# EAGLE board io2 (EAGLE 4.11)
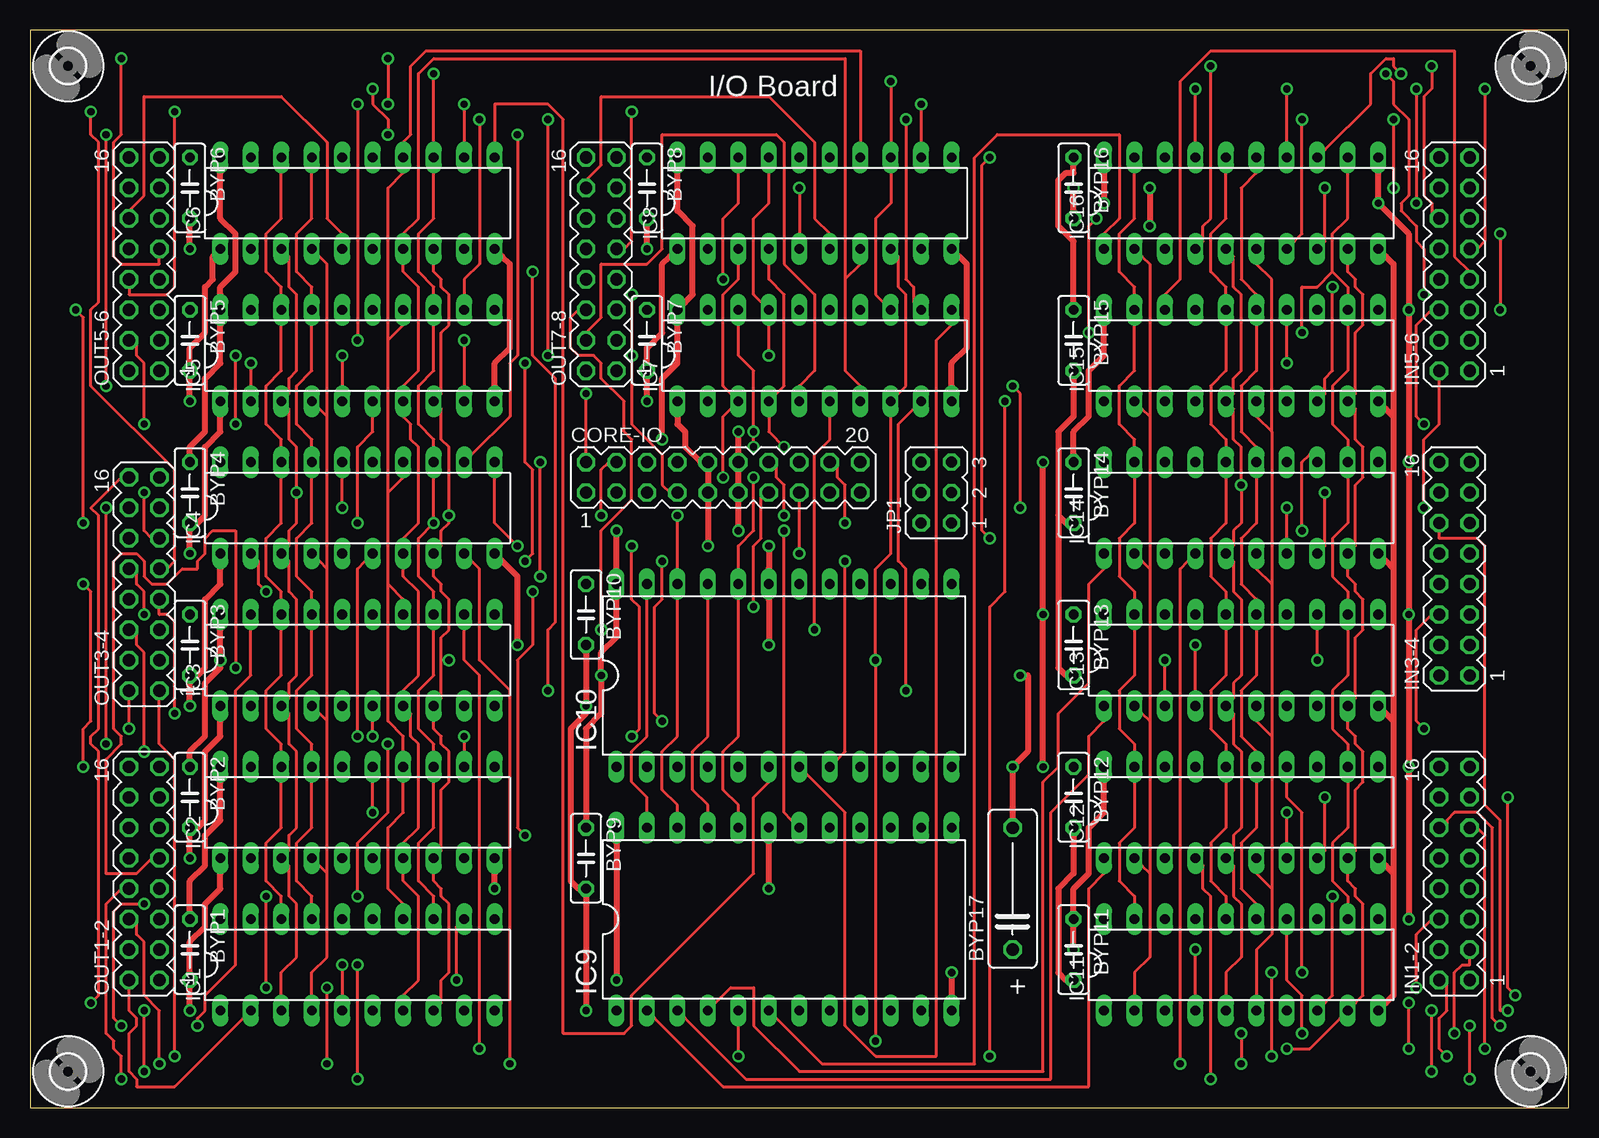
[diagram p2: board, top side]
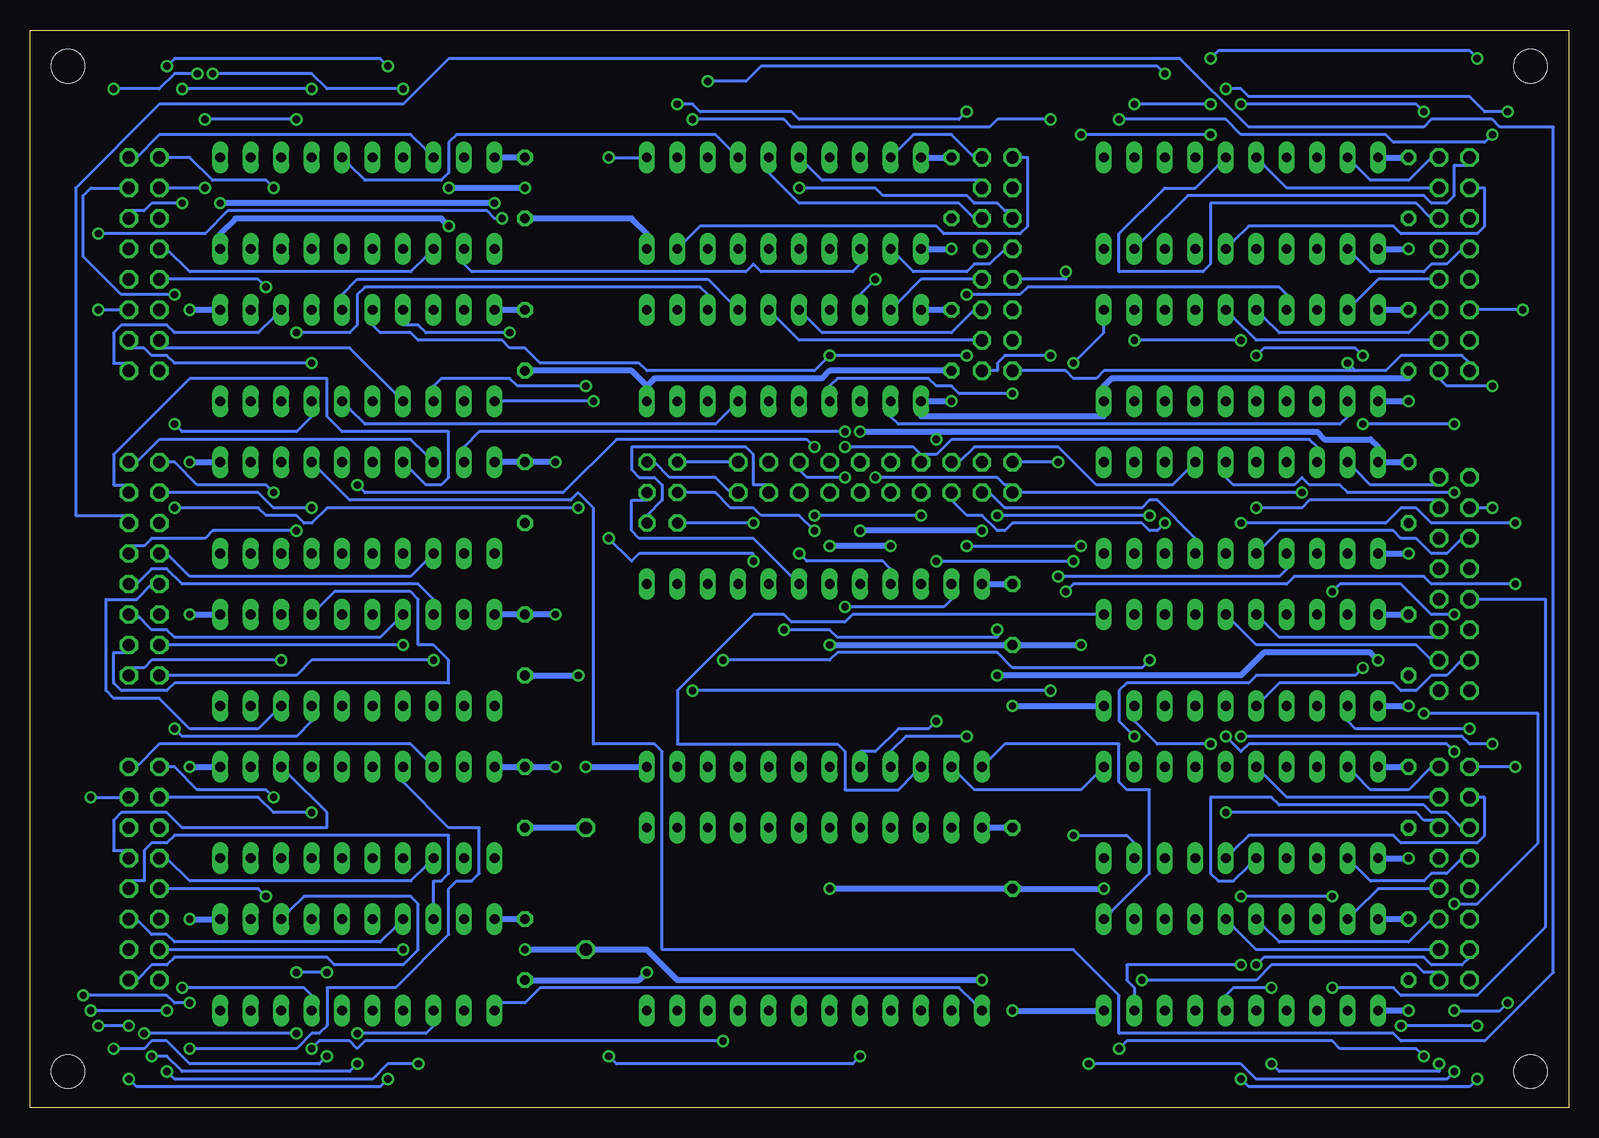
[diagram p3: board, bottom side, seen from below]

Size 128.25 x 89.84 mm. Coordinates in mm from the lower left corner, seen from the top.
Outline: 0,0 128.25,0 128.25,89.84 0,89.84 0,0
Copper layers (1*16): Top 0.035mm / dielectric 1.5mm / Bottom 0.035mm
Design rules "default": minimum track width 10mil, minimum drill 24mil, track to track 8mil, track to pad 8mil, pad to pad 8mil, via to via 8mil, smd to smd 8mil, copper to edge 40mil, drill to drill 8mil, minimum pad ring 10mil, minimum via ring 8mil, stop-mask expansion 4mil, vias tented up to drill 0mil, thermal gap 10mil
Net classes: 1 Power: width 0.508 mm, drill 0.254 mm, clearance 0.254 mm

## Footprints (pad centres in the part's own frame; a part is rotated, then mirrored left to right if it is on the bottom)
C050-025X075 = drill 0.813 octagon: 1 -2.54,0; 2 2.54,0
C102-043X133 = drill 1.016 octagon: 1 -5.08,0; 2 5.08,0
MA10-2 = drill 1.016 octagon: 1 -11.43,-1.27; 2 -11.43,1.27; 3 -8.89,-1.27; 4 -8.89,1.27; 5 -6.35,-1.27; 6 -6.35,1.27; 7 -3.81,-1.27; 8 -3.81,1.27; 9 -1.27,-1.27; 10 -1.27,1.27; 11 1.27,-1.27; 12 1.27,1.27; 13 3.81,-1.27; 14 3.81,1.27; 15 6.35,-1.27; 16 6.35,1.27; 17 8.89,-1.27; 18 8.89,1.27; 19 11.43,-1.27; 20 11.43,1.27
DIL20 = drill 0.813 long: 1 -11.43,-3.81; 2 -8.89,-3.81; 3 -6.35,-3.81; 4 -3.81,-3.81; 5 -1.27,-3.81; 6 1.27,-3.81; 7 3.81,-3.81; 8 6.35,-3.81; 9 8.89,-3.81; 10 11.43,-3.81; 11 11.43,3.81; 12 8.89,3.81; 13 6.35,3.81; 14 3.81,3.81; 15 1.27,3.81; 16 -1.27,3.81; 17 -3.81,3.81; 18 -6.35,3.81; 19 -8.89,3.81; 20 -11.43,3.81
DIL24-6 = drill 0.813 long: 1 -13.97,-7.62; 2 -11.43,-7.62; 3 -8.89,-7.62; 4 -6.35,-7.62; 5 -3.81,-7.62; 6 -1.27,-7.62; 7 1.27,-7.62; 8 3.81,-7.62; 9 6.35,-7.62; 10 8.89,-7.62; 11 11.43,-7.62; 12 13.97,-7.62; 13 13.97,7.62; 14 11.43,7.62; 15 8.89,7.62; 16 6.35,7.62; 17 3.81,7.62; 18 1.27,7.62; 19 -1.27,7.62; 20 -3.81,7.62; 21 -6.35,7.62; 22 -8.89,7.62; 23 -11.43,7.62; 24 -13.97,7.62
MA08-2 = drill 1.016 octagon: 1 -8.89,-1.27; 2 -8.89,1.27; 3 -6.35,-1.27; 4 -6.35,1.27; 5 -3.81,-1.27; 6 -3.81,1.27; 7 -1.27,-1.27; 8 -1.27,1.27; 9 1.27,-1.27; 10 1.27,1.27; 11 3.81,-1.27; 12 3.81,1.27; 13 6.35,-1.27; 14 6.35,1.27; 15 8.89,-1.27; 16 8.89,1.27
JP3Q = drill 0.914 octagon: 1 -2.54,-1.27; 2 -2.54,1.27; 3 0,-1.27; 4 0,1.27; 5 2.54,-1.27; 6 2.54,1.27
2,8 = hole 2.8: 0,0

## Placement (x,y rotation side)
BYP1  .01uf  [C050-025X075]  13.33,13.17 270 top
BYP2  .01uf  [C050-025X075]  13.33,25.87 270 top
BYP3  .01uf  [C050-025X075]  13.33,38.57 270 top
BYP4  .01uf  [C050-025X075]  13.33,51.27 270 top
BYP5  .01uf  [C050-025X075]  13.33,63.97 270 top
BYP6  .01uf  [C050-025X075]  13.33,76.67 270 top
BYP7  .01uf  [C050-025X075]  51.43,63.97 270 top
BYP8  .01uf  [C050-025X075]  51.43,76.67 270 top
BYP9  .01uf  [C050-025X075]  46.35,20.79 270 top
BYP10  .01uf  [C050-025X075]  46.35,41.11 270 top
BYP11  .01uf  [C050-025X075]  86.99,13.17 270 top
BYP12  .01uf  [C050-025X075]  86.99,25.87 270 top
BYP13  .01uf  [C050-025X075]  86.99,38.57 270 top
BYP14  .01uf  [C050-025X075]  86.99,51.27 270 top
BYP15  .01uf  [C050-025X075]  86.99,63.97 270 top
BYP16  .01uf  [C050-025X075]  86.99,76.67 270 top
BYP17  100uf 25V  [C102-043X133]  81.91,18.25 90 top
CORE-IO  [MA10-2]  57.78,52.54 0 top
IC1  74LS374N  [DIL20]  27.3,11.9 0 top
IC2  74LS374N  [DIL20]  27.3,24.6 0 top
IC3  74LS374N  [DIL20]  27.3,37.3 0 top
IC4  74LS374N  [DIL20]  27.3,50 0 top
IC5  74LS374N  [DIL20]  27.3,62.7 0 top
IC6  74LS374N  [DIL20]  27.3,75.4 0 top
IC7  74LS374N  [DIL20]  65.4,62.7 0 top
IC8  74LS374N  [DIL20]  65.4,75.4 0 top
IC9  74154N  [DIL24-6]  62.86,15.71 0 top
IC10  74154N  [DIL24-6]  62.86,36.03 0 top
IC11  74LS373N  [DIL20]  100.96,11.9 0 top
IC12  74LS373N  [DIL20]  100.96,24.6 0 top
IC13  74LS373N  [DIL20]  100.96,37.3 0 top
IC14  74LS373N  [DIL20]  100.96,50 0 top
IC15  74LS373N  [DIL20]  100.96,62.7 0 top
IC16  74LS373N  [DIL20]  100.96,75.4 0 top
IN1-2  [MA08-2]  118.74,19.52 90 top
IN3-4  [MA08-2]  118.74,44.92 90 top
IN5-6  [MA08-2]  118.74,70.32 90 top
JP1  [JP3Q]  75.56,51.27 90 top
OUT1-2  [MA08-2]  9.52,19.52 90 top
OUT3-4  [MA08-2]  9.52,43.65 90 top
OUT5-6  [MA08-2]  9.52,70.32 90 top
OUT7-8  [MA08-2]  47.62,70.32 90 top
U$1  [2,8]  125.09,3.01 0 top
U$2  [2,8]  125.09,86.83 0 top
U$3  [2,8]  3.17,86.83 0 top
U$4  [2,8]  3.17,3.01 0 top

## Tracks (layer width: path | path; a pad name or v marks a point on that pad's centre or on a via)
GND  (via drill 0.61)
  Top 0.508: 113.66,19.52 113.66,9.36 113.02,8.73 IC11.10 | 113.66,19.52 113.02,20.15 IC12.10 | 113.66,32.22 113.02,32.85 IC13.10 | 113.66,32.22 113.66,19.52 | 113.66,44.92 113.02,45.55 IC14.10 | 113.66,44.92 113.66,32.22 | 113.66,57.62 113.02,58.25 IC15.10 | 113.66,57.62 113.66,44.92 | 113.66,57.62 113.66,70.32 113.02,70.95 IC16.10 | 85.72,49.37 86.35,48.73 BYP14.2 | 85.72,49.37 85.72,56.35 86.99,57.62 86.99,60.8 BYP15.2 | IC8.10 77.46,70.95 78.1,70.32 78.1,63.34 76.83,62.06 76.83,60.16 IC7.10 | v76.83,11.27 76.83,9.36 IC9.12 | BYP17.2 81.91,23.96 v81.91,28.41 83.18,29.68 83.18,36.03 v82.55,36.03 | BYP11.2 86.35,10.63 85.72,11.27 85.72,18.25 86.99,19.52 86.99,22.7 BYP12.2 | 85.72,49.37 85.72,36.66 86.35,36.03 BYP13.2 | v93.34,76.67 v93.34,73.5 | v86.99,76.67 86.99,74.77 BYP16.2 | v13.33,8.09 13.33,10 BYP1.2 13.33,11.27 13.33,13.81 14.6,15.08 14.6,16.98 15.87,18.25 15.87,19.52 IC2.1 | v13.33,20.79 13.33,22.7 BYP2.2 13.97,23.33 14.6,23.96 14.6,29.68 15.87,30.95 15.87,32.22 IC3.1 | v13.33,71.59 13.33,73.5 BYP6.2 | v13.33,58.89 13.33,60.8 BYP5.2 13.33,62.06 13.33,63.34 14.6,64.61 14.6,68.41 15.24,69.05 15.24,70.95 IC6.1 | v13.33,33.49 13.33,35.39 BYP3.2 13.97,36.03 14.6,36.66 14.6,42.38 15.87,43.65 15.87,44.92 IC4.1 | v13.33,46.19 13.33,48.09 BYP4.2 13.97,48.73 14.6,49.37 14.6,55.08 15.87,56.35 15.87,57.62 IC5.1 | v46.35,8.09 46.35,17.61 BYP9.2 45.72,18.25 45.08,18.88 45.08,31.58 46.35,32.85 v46.35,33.49 46.35,37.94 BYP10.2 | v38.73,18.25 38.73,19.52 IC2.10 | v61.59,18.25 61.59,22.06 IC9.19 | v40.64,38.57 40.64,44.28 39.37,45.55 IC4.10 | v61.59,38.57 61.59,42.38 IC10.19 61.59,44.92 v61.59,46.82
  Top 0.508: v51.43,71.59 51.43,73.5 BYP8.2 | IC6.10 39.37,70.95 40,70.32 40,63.34 38.73,62.06 38.73,60.16 IC5.10 | v51.43,58.89 51.43,60.8 BYP7.2 51.43,62.06 51.43,63.34 52.7,64.61 52.7,70.32 53.34,70.95 IC8.1 | IC7.1 53.97,57.62 53.97,56.98 54.61,56.35 54.61,55.08 55.88,53.81 CORE-IO.10 56.51,53.17 56.51,51.91 CORE-IO.9 56.51,50.63 v56.51,46.82
  Bottom 0.508: IC8.10 76.83,72.86 78.1,74.13 86.35,74.13 BYP16.2 | 76.83,60.16 78.1,61.43 86.35,61.43 BYP15.2 | 76.83,60.16 IC7.10 76.83,60.16 | v76.83,11.27 77.46,10.63 86.35,10.63 BYP11.2 | v81.91,28.41 77.46,28.41 IC10.12 | BYP12.2 86.35,23.33 82.55,23.33 BYP17.2 | v82.55,36.03 86.35,36.03 BYP13.2 | v93.34,73.5 93.97,74.13 111.12,74.13 112.39,72.86 IC16.10 | v86.99,76.67 v93.34,76.67 | v13.33,8.09 15.24,8.09 IC1.1 | v13.33,20.79 15.24,20.79 IC2.1 | v13.33,71.59 15.24,71.59 IC6.1 | v13.33,58.89 15.24,58.89 IC5.1 | v13.33,33.49 15.24,33.49 IC3.1 | v13.33,46.19 15.24,46.19 IC4.1 | v46.35,8.09 39.37,8.09 IC1.10 | v38.73,18.25 45.72,18.25 BYP9.2 46.98,18.25 v61.59,18.25 | v46.35,33.49 39.37,33.49 IC3.10 | v40.64,38.57 45.72,38.57 BYP10.2 46.98,38.57 v61.59,38.57 | v51.43,71.59 53.34,71.59 IC8.1 | v51.43,58.89 53.34,58.89 IC7.1 53.97,57.62 38.73,57.62 IC5.10 38.73,60.16 38.1,60.8 13.33,60.8 BYP5.2 | v56.51,46.82 v61.59,46.82 | 76.83,60.16 76.19,60.8 62.23,60.8 61.59,61.43 52.07,61.43 BYP7.2
IN00
  Bottom 0.254: IC9.1 49.53,8.73 50.8,10 85.72,10 86.99,8.73 88.89,8.73 IC11.1
IN01
  Top 0.254: IC9.2 52.07,7.46 57.78,1.74 88.26,1.74 88.26,18.25 89.53,19.52 IC12.1
IN02
  Top 0.254: IC9.3 54.61,7.46 59.69,2.38 85.08,2.38 85.08,24.6 88.26,27.77 88.26,30.95 89.53,32.22 IC13.1
IN03
  Top 0.254: IC9.4 57.15,8.73 58.41,10 60.32,10 60.32,6.82 64.13,3.01 84.45,3.01 84.45,27.14 85.72,28.41 85.72,32.85 88.26,35.39 88.26,43.65 89.53,44.92 IC14.1
IN04  (via drill 0.61)
  Top 0.254: v59.05,4.28 59.05,6.82 IC9.5 | v80,4.28 80,41.74 81.27,43.02 v81.27,58.89
  Bottom 0.254: v59.05,4.28 59.69,3.64 79.37,3.64 v80,4.28 | v81.27,58.89 88.89,58.89 IC15.1
IN05
  Top 0.254: IC9.6 62.23,7.46 66.03,3.64 78.73,3.64 78.73,79.21 80.64,81.11 90.8,81.11 90.8,74.13 89.53,72.86 IC16.1
ISEL  (via drill 0.61)
  Top 0.254: v62.86,48.09 62.86,24.6 63.5,23.96 IC9.18
  Bottom 0.254: v62.86,48.09 64.13,49.37 67.3,49.37 67.94,50 69.84,50 71.11,51.27 73.66,51.27 JP1.4
N$1
  Bottom 0.254: IC12.3 95.24,20.15 96.52,18.88 114.93,18.88 116.83,20.79 IN1-2.10
N$2  (via drill 0.61)
  Top 0.254: v98.42,2.38 98.42,17.61 97.78,18.25 97.78,20.15 IC12.4 | v120.01,2.38 v120.01,6.82 | v122.55,6.82 121.91,7.46 121.91,23.33 120.64,24.6 118.74,24.6 118.1,23.96 118.1,23.33 IN1-2.12
  Bottom 0.254: v98.42,2.38 99.05,1.74 119.38,1.74 v120.01,2.38 | v120.01,6.82 v122.55,6.82
N$7  (via drill 0.61)
  Top 0.254: v104.77,24.6 104.77,22.06 IC12.7
  Bottom 0.254: v104.77,24.6 107.94,24.6 109.21,25.87 116.83,25.87 IN1-2.14
N$8  (via drill 0.61)
  Top 0.254: v107.94,25.87 107.94,21.42 IC12.8
  Bottom 0.254: v107.94,25.87 108.58,26.5 114.3,26.5 116.2,28.41 116.83,28.41 IN1-2.16
N$9  (via drill 0.61)
  Top 0.254: v108.58,17.61 108.58,9.36 107.94,8.73 IC11.8
  Bottom 0.254: v108.58,17.61 109.21,18.25 116.83,18.25 IN1-2.8
N$10  (via drill 0.61)
  Top 0.254: v115.56,10 115.56,14.44 116.83,15.71 IN1-2.6
  Bottom 0.254: v115.56,10 105.41,10 104.77,9.36 IC11.7
N$11  (via drill 0.61)
  Top 0.254: v97.15,13.17 97.15,9.36 IC11.4
  Bottom 0.254: v97.15,13.17 116.83,13.17 IN1-2.4
N$12  (via drill 0.61)
  Top 0.254: v100.96,6.18 v100.96,3.64 | v118.1,4.28 117.47,4.92 117.47,7.46 118.1,8.09 118.1,10.63 IN1-2.2
  Bottom 0.254: v100.96,6.18 95.24,6.18 94.61,6.82 IC11.3 | v100.96,3.64 101.59,3.01 115.56,3.01 116.83,4.28 v118.1,4.28
N$13
  Bottom 0.254: IC11.13 106.67,16.34 105.41,17.61 96.52,17.61 95.88,16.98 95.88,13.17 97.15,11.9 102.86,11.9 103.5,12.54 116.2,12.54 116.83,11.9 118.1,11.9 119.38,10.63 IN1-2.1
N$14  (via drill 0.61)
  Top 0.254: v106.04,6.18 106.04,9.36 104.77,10.63 104.77,14.44 IC11.14 | v118.74,6.18 118.74,11.27 119.38,11.9 120.01,11.9 120.01,12.54 IN1-2.3
  Bottom 0.254: v106.04,6.18 v118.74,6.18
N$15
  Bottom 0.254: IC11.17 97.78,15.08 99.05,13.81 116.2,13.81 116.83,14.44 118.1,14.44 119.38,15.71 IN1-2.5
N$16
  Bottom 0.254: IC11.18 94.61,16.98 94.61,18.88 93.97,18.88 93.34,19.52 93.34,22.7 116.2,22.7 116.83,22.06 118.1,22.06 118.74,21.42 118.74,18.88 120.01,18.88 IN1-2.7
N$17
  Bottom 0.254: IC12.13 106.67,27.77 103.5,24.6 103.5,23.33 115.56,23.33 116.83,24.6 120.64,24.6 121.28,23.96 121.28,21.42 120.01,21.42 IN1-2.9
N$18  (via drill 0.61)
  Top 0.254: v121.28,4.92 121.28,22.7 120.64,23.33 IN1-2.11 | v103.5,4.28 v103.5,11.27 | v106.04,11.27 106.04,24.6 104.77,25.87 104.77,27.14 IC12.14
  Bottom 0.254: v121.28,4.92 118.74,4.92 118.1,5.55 116.83,5.55 114.93,3.64 104.13,3.64 v103.5,4.28 | v103.5,11.27 v106.04,11.27
N$19  (via drill 0.61)
  Top 0.254: v123.19,25.87 123.19,10 v123.82,9.36 | v114.93,4.92 v114.93,8.73
  Bottom 0.254: v123.19,25.87 120.64,25.87 IN1-2.13 | v123.82,9.36 116.83,9.36 116.2,8.73 v114.93,8.73 | v114.93,4.92 106.04,4.92 104.77,6.18 104.13,6.18 103.5,6.82 103.5,10 97.78,10 93.34,14.44 93.34,18.25 92.7,18.88 91.44,18.88 90.8,19.52 90.8,23.33 93.34,23.33 97.15,27.14 IC12.17
N$20
  Bottom 0.254: IC12.18 95.24,29.04 96.52,30.31 117.47,30.31 119.38,28.41 IN1-2.15
N$26  (via drill 0.61)
  Top 0.254: v18.41,62.06 18.41,60.16 IC5.2
  Bottom 0.254: 17.77,61.43 15.24,61.43 13.97,62.7 8.89,62.7 8.25,62.06 OUT5-6.2 | 17.77,61.43 v18.41,62.06 | IC7.2 56.51,57.62 55.88,56.98 19.04,56.98 18.41,57.62 IC5.2 | 17.77,61.43 38.73,61.43 39.37,60.8 41.27,60.8 41.91,61.43 45.72,61.43 OUT7-8.2
N$29
  Bottom 0.254: IC14.3 95.24,45.55 96.52,44.28 114.93,44.28 116.83,46.19 IN3-4.10
N$30  (via drill 0.61)
  Top 0.254: v95.88,3.64 95.88,44.92 96.52,45.55 IC14.4 | v116.83,3.01 v116.83,8.09 | v123.19,8.09 122.55,8.09 122.55,23.96 121.28,25.23 121.28,46.82 120.64,47.46 117.47,47.46 117.47,48.09 IN3-4.12
  Bottom 0.254: v95.88,3.64 98.42,3.64 99.69,2.38 116.2,2.38 v116.83,3.01 | v116.83,8.09 v123.19,8.09
N$31  (via drill 0.61)
  Top 0.254: v104.77,50 104.77,47.46 IC14.7
  Bottom 0.254: v104.77,50 107.94,50 109.21,51.27 116.83,51.27 IN3-4.14
N$32  (via drill 0.61)
  Top 0.254: v107.94,51.27 107.94,46.82 IC14.8
  Bottom 0.254: v107.94,51.27 108.58,51.91 114.3,51.91 116.2,53.81 116.83,53.81 IN3-4.16
N$33  (via drill 0.61)
  Top 0.254: v37.46,4.92 37.46,36.03 36.19,37.3 36.19,39.84 IC3.12 | v12.06,4.28 12.06,29.04 10.79,30.31 10.79,34.12 OUT3-4.1
  Bottom 0.254: v37.46,4.92 36.83,5.55 19.68,5.55 19.04,4.92 12.7,4.92 v12.06,4.28
N$34
  Bottom 0.254: IC3.15 27.93,40.48 26.03,38.57 12.7,38.57 11.43,37.3 OUT3-4.3
N$35
  Bottom 0.254: IC3.16 25.39,40.48 24.12,39.2 10.79,39.2 OUT3-4.5
N$36  (via drill 0.61)
  Top 0.254: v13.97,6.82 13.97,7.46 14.6,8.09 14.6,9.36 17.14,11.9 17.14,34.76 18.41,36.03 18.41,39.84 IC3.19 | v7.62,6.82 6.98,7.46 6.98,16.34 7.62,16.98 v9.52,16.98 | v12.06,32.85 12.06,40.48 11.43,41.11 10.79,41.11 10.79,41.74 OUT3-4.7
  Bottom 0.254: v7.62,6.82 v13.97,6.82 | v9.52,16.98 7.62,16.98 2.54,22.06 2.54,32.85 v12.06,32.85
N$37  (via drill 0.61)
  Top 0.254: v94.61,37.3 94.61,34.76 IC13.3
  Bottom 0.254: v94.61,37.3 104.77,37.3 106.04,36.03 116.83,36.03 IN3-4.2
N$38  (via drill 0.61)
  Top 0.254: v97.15,38.57 97.15,34.76 IC13.4
  Bottom 0.254: v97.15,38.57 116.83,38.57 IN3-4.4
N$39  (via drill 0.61)
  Top 0.254: v116.2,31.58 115.56,32.22 115.56,39.84 116.83,41.11 IN3-4.6
  Bottom 0.254: v116.2,31.58 115.56,30.95 106.04,30.95 104.77,32.22 IC13.7
N$40
  Bottom 0.254: IC13.8 107.94,32.85 109.21,31.58 114.93,31.58 117.47,34.12 121.28,34.12 121.91,34.76 121.91,42.38 119.38,42.38 118.1,43.65 IN3-4.8
N$41  (via drill 0.61)
  Top 0.254: v106.04,48.09 106.04,53.81 106.67,54.45 IC14.13
  Bottom 0.254: v106.04,48.09 113.02,48.09 113.66,47.46 118.1,47.46 118.74,46.82 120.01,46.82 IN3-4.9
N$42
  Bottom 0.254: IC14.14 104.13,53.17 101.59,50.63 83.18,50.63 82.55,51.27 81.27,50 81.27,30.31 76.19,30.31 75.56,29.68 75.56,13.17 41.27,13.17 37.46,9.36 37.46,6.18 14.6,6.18 13.97,5.55 6.98,5.55 1.27,11.27 1.27,81.75 5.71,81.75 6.34,82.39 11.43,82.39 12.06,81.75 26.66,81.75 32.38,87.47 93.34,87.47 97.15,83.66 117.47,83.66 124.45,76.67 124.45,49.37 120.01,49.37 IN3-4.11
N$43
  Bottom 0.254: IC14.17 96.52,53.17 95.24,51.91 93.97,51.91 93.34,52.54 93.34,56.35 102.23,56.35 103.5,57.62 103.5,60.8 114.93,60.8 121.28,54.45 121.28,51.91 120.01,51.91 IN3-4.13
N$44
  Bottom 0.254: IC14.18 95.24,54.45 96.52,55.71 117.47,55.71 119.38,53.81 IN3-4.15
N$45  (via drill 0.61)
  Top 0.254: v107.31,37.3 107.31,39.84 IC13.13
  Bottom 0.254: v107.31,37.3 118.1,37.3 118.74,36.66 120.01,36.66 IN3-4.1
N$46
  Bottom 0.254: IC13.14 104.13,41.74 102.86,43.02 96.52,43.02 95.88,42.38 95.88,38.57 94.61,38.57 93.34,37.3 93.34,35.39 116.2,35.39 116.83,34.76 120.64,34.76 121.28,35.39 121.28,37.94 120.01,37.94 IN3-4.3
N$47
  Bottom 0.254: IC13.17 97.78,40.48 99.05,39.2 116.2,39.2 116.83,39.84 118.1,39.84 119.38,41.11 IN3-4.5
N$48
  Bottom 0.254: IC13.18 94.61,42.38 95.88,43.65 115.56,43.65 116.83,44.92 118.1,44.92 119.38,43.65 IN3-4.7
N$49
  Bottom 0.254: IC3.5 25.39,34.12 24.12,35.39 14.6,35.39 13.97,34.76 12.7,34.76 11.43,36.03 10.16,36.03 8.89,37.3 OUT3-4.4
N$50  (via drill 0.61)
  Top 0.254: v28.57,30.95 28.57,32.22 IC3.6 | v9.52,29.68 9.52,37.94 8.89,38.57 8.89,39.84 OUT3-4.6
  Bottom 0.254: v28.57,30.95 27.3,29.68 26.66,30.31 10.16,30.31 v9.52,29.68
N$51  (via drill 0.61)
  Top 0.254: v8.25,31.58 8.25,34.12 OUT3-4.2
  Bottom 0.254: v8.25,31.58 17.77,31.58 18.41,32.22 IC3.2
N$52  (via drill 0.61)
  Top 0.254: v29.84,30.31 29.84,24.6 27.3,22.06 v27.3,17.61 | v19.68,10 v19.68,17.61
  Bottom 0.254: v29.84,30.31 34.29,30.31 36.19,32.22 IC3.9 | v19.68,17.61 v27.3,17.61 | v19.68,10 14.6,10 13.97,9.36 7.62,9.36 1.9,15.08 1.9,42.38 7.62,42.38 OUT3-4.8
N$53  (via drill 0.61)
  Top 0.254: v35.55,10.63 35.55,15.08 IC1.12
  Bottom 0.254: v35.55,10.63 26.03,10.63 24.76,11.9 12.7,11.9 12.06,11.27 10.79,11.27 OUT1-2.1
N$54
  Bottom 0.254: IC1.15 27.93,15.08 26.03,13.17 11.43,13.17 OUT1-2.3
N$55
  Bottom 0.254: IC1.16 25.39,15.08 24.12,13.81 13.33,13.81 11.43,15.71 OUT1-2.5
N$56
  Bottom 0.254: IC1.19 17.77,16.34 15.87,18.25 11.43,18.25 OUT1-2.7
N$57
  Top 0.254: IC1.2 17.77,7.46 12.06,1.74 8.89,1.74 8.89,2.38 8.25,3.01 8.25,6.18 8.89,6.82 8.89,7.46 8.25,8.09 8.25,10 OUT1-2.2
N$58  (via drill 0.61)
  Top 0.254: v26.03,11.9 26.03,9.36 IC1.5
  Bottom 0.254: v26.03,11.9 25.39,12.54 12.06,12.54 11.43,11.9 8.89,11.9 8.25,12.54 OUT1-2.4
N$59  (via drill 0.61)
  Top 0.254: v10.79,3.64 10.79,8.09 9.52,9.36 9.52,13.81 8.89,14.44 8.89,15.71 OUT1-2.6 | v24.76,3.64 v24.76,10
  Bottom 0.254: v10.79,3.64 10.79,3.01 24.12,3.01 v24.76,3.64 | v24.76,10 27.93,10 28.57,9.36 IC1.6
N$60  (via drill 0.61)
  Top 0.254: v27.3,2.38 v27.3,11.9 | v7.62,2.38 7.62,4.28 6.98,4.92 6.98,5.55 6.34,6.18 6.34,16.98 7.62,18.25 OUT1-2.8
  Bottom 0.254: v27.3,11.9 36.83,11.9 36.83,10.63 36.19,10 36.19,9.36 IC1.9 | v27.3,2.38 26.66,1.74 8.25,1.74 v7.62,2.38
N$61
  Bottom 0.254: IC2.19 17.77,27.77 16.5,26.5 13.33,26.5 11.43,28.41 OUT1-2.15
N$62
  Bottom 0.254: IC2.16 25.39,27.77 23.49,25.87 11.43,25.87 OUT1-2.13
N$63  (via drill 0.61)
  Top 0.254: v28.57,24.6 28.57,27.14 IC2.15
  Bottom 0.254: v28.57,24.6 12.7,24.6 12.06,23.96 10.79,23.96 OUT1-2.11
N$64  (via drill 0.61)
  Top 0.254: v17.14,36.66 17.14,48.09 15.24,48.09 14.6,47.46 14.6,46.19 13.97,45.55 13.97,44.92 12.7,44.92 11.43,43.65 10.16,43.65 9.52,44.28 9.52,45.55 8.89,46.19 7.62,46.19 6.98,45.55 6.98,31.58 7.62,30.95 7.62,30.31 6.34,29.04 6.34,19.52 8.89,19.52 10.16,20.79 OUT1-2.9 | v36.19,30.95 36.19,29.68 IC2.12
  Bottom 0.254: v17.14,36.66 17.77,36.03 26.03,36.03 26.66,35.39 36.83,35.39 37.46,34.76 37.46,32.22 v36.19,30.95
N$65
  Bottom 0.254: IC2.2 17.77,20.15 16.5,18.88 12.06,18.88 11.43,19.52 10.16,19.52 8.89,20.79 OUT1-2.10
N$66
  Bottom 0.254: IC2.5 26.66,20.15 27.93,18.88 29.2,18.88 29.84,19.52 29.84,25.87 24.76,25.87 24.12,25.23 12.06,25.23 11.43,24.6 10.16,24.6 8.89,23.33 OUT1-2.12
N$67
  Bottom 0.254: IC2.6 27.93,21.42 26.66,22.7 14.6,22.7 13.97,22.06 7.62,22.06 6.98,22.7 6.98,25.87 7.62,25.87 OUT1-2.14
N$68  (via drill 0.61)
  Top 0.254: v41.27,22.7 40.64,23.33 40.64,37.3 41.91,38.57 v41.91,43.02 | v4.44,43.65 5.08,43.02 5.08,32.22 4.44,31.58 v4.44,28.41
  Bottom 0.254: v41.27,22.7 36.83,22.7 36.19,22.06 IC2.9 | v41.91,43.02 41.27,43.65 23.49,43.65 22.86,44.28 12.06,44.28 11.43,43.65 v4.44,43.65 | v4.44,28.41 7.62,28.41 OUT1-2.16
N$69  (via drill 0.61)
  Top 0.254: v9.52,41.11 9.52,43.02 8.89,43.65 8.89,44.92 OUT3-4.10 | v19.68,43.02 19.04,43.65 19.04,45.55 IC4.2
  Bottom 0.254: v9.52,41.11 11.43,41.11 13.97,43.65 19.04,43.65 v19.68,43.02
N$70
  Bottom 0.254: IC4.5 25.39,46.82 24.12,48.09 14.6,48.09 13.97,47.46 12.7,47.46 11.43,46.19 10.16,46.19 8.89,47.46 OUT3-4.12
N$71  (via drill 0.61)
  Top 0.254: v27.3,30.95 27.3,44.92 27.93,45.55 IC4.6 | v6.34,30.31 v6.34,50
  Bottom 0.254: v27.3,30.95 8.89,30.95 8.25,30.31 v6.34,30.31 | v6.34,50 7.62,50 OUT3-4.14
N$72  (via drill 0.61)
  Top 0.254: v40,3.64 40,34.76 37.46,37.3 37.46,44.92 36.83,45.55 IC4.9 | v9.52,3.01 v9.52,8.09 | v5.08,8.73 5.71,9.36 5.71,29.68 5.08,30.31 5.08,30.95 5.71,31.58 5.71,49.37 5.08,50 7.62,52.54 OUT3-4.16
  Bottom 0.254: v40,3.64 27.3,3.64 26.03,2.38 10.16,2.38 v9.52,3.01 | v9.52,8.09 5.71,8.09 v5.08,8.73
N$73
  Bottom 0.254: IC4.19 17.77,53.17 16.5,51.91 10.79,51.91 OUT3-4.15
N$74  (via drill 0.61)
  Top 0.254: v26.03,50 26.03,52.54 IC4.16
  Bottom 0.254: v26.03,50 22.22,50 21.58,50.63 10.79,50.63 OUT3-4.13
N$75  (via drill 0.61)
  Top 0.254: v9.52,51.27 9.52,48.09 10.16,47.46 OUT3-4.11
  Bottom 0.254: v9.52,51.27 18.41,51.27 19.04,51.91 21.58,51.91 22.22,52.54 22.86,51.91 27.93,51.91 28.57,52.54 IC4.15
N$76  (via drill 0.61)
  Top 0.254: v40.64,81.11 40.64,62.7 40,62.06 40,57.62 36.83,54.45 IC4.12 | v29.84,81.11 29.84,82.39 28.57,83.66 v28.57,84.92 | v5.08,83.02 5.08,81.11 5.71,80.48 5.71,67.14 5.08,66.51 5.08,60.16 12.06,53.17 12.06,45.55 11.43,44.92 OUT3-4.9
  Bottom 0.254: v29.84,81.11 v40.64,81.11 | v28.57,84.92 27.3,84.92 26.66,84.29 8.25,84.29 6.98,83.02 v5.08,83.02
N$77
  Bottom 0.254: IC16.3 95.24,70.95 96.52,69.69 114.93,69.69 116.83,71.59 IN5-6.10
N$78  (via drill 0.61)
  Top 0.254: v98.42,86.83 98.42,74.13 97.78,73.5 97.78,72.22 IC16.4 | v116.83,86.83 116.83,84.92 116.2,84.29 116.2,76.03 116.83,75.4 116.83,74.13 IN5-6.12
  Bottom 0.254: v98.42,86.83 99.05,87.47 116.2,87.47 v116.83,86.83
N$79  (via drill 0.61)
  Top 0.254: v106.04,82.39 106.04,72.86 105.41,72.22 IC16.7 | v113.66,82.39 v113.66,76.67
  Bottom 0.254: v106.04,82.39 v113.66,82.39 | v113.66,76.67 116.83,76.67 IN5-6.14
N$80  (via drill 0.61)
  Top 0.254: v107.94,76.67 107.94,72.22 IC16.8
  Bottom 0.254: v107.94,76.67 108.58,77.3 113.02,77.3 114.93,79.21 116.83,79.21 IN5-6.16
N$81  (via drill 0.61)
  Top 0.254: v6.34,60.16 v6.34,81.11 | v37.46,82.39 37.46,70.32 36.19,69.05 36.19,67.78 IC5.12
  Bottom 0.254: v6.34,60.16 10.16,60.16 10.79,60.8 OUT5-6.1 | v6.34,81.11 6.98,80.48 14.6,80.48 15.24,81.11 27.3,81.11 28.57,82.39 v37.46,82.39
N$82
  Bottom 0.254: IC5.15 27.93,65.88 26.03,63.97 11.43,63.97 OUT5-6.3
N$83
  Bottom 0.254: IC5.16 25.39,65.88 24.12,64.61 13.33,64.61 11.43,66.51 OUT5-6.5
N$84
  Bottom 0.254: IC5.19 17.77,67.14 15.87,69.05 11.43,69.05 OUT5-6.7
N$85  (via drill 0.61)
  Top 0.254: v73.02,82.39 73.02,69.05 73.66,68.41 73.66,67.14 IC7.12 | v43.18,62.7 v43.18,82.39
  Bottom 0.254: v73.02,82.39 65.4,82.39 64.77,81.75 48.26,81.75 47.62,82.39 v43.18,82.39 | v43.18,62.7 46.98,62.7 47.62,62.06 47.62,61.43 48.26,61.43 OUT7-8.1
N$86
  Bottom 0.254: IC7.15 66.03,65.88 64.13,63.97 49.53,63.97 OUT7-8.3
N$87
  Bottom 0.254: IC7.16 63.5,65.88 62.23,64.61 51.43,64.61 49.53,66.51 OUT7-8.5
N$88
  Bottom 0.254: IC7.19 55.88,67.14 53.97,69.05 49.53,69.05 OUT7-8.7
N$89  (via drill 0.61)
  Top 0.254: v26.03,62.7 26.03,60.16 IC5.5 | v17.14,56.98 v17.14,62.7 | v9.52,56.98 9.52,62.06 8.89,62.7 8.89,63.97 OUT5-6.4
  Bottom 0.254: v26.03,62.7 25.39,63.34 17.77,63.34 v17.14,62.7 | v9.52,56.98 v17.14,56.98
N$90  (via drill 0.61)
  Top 0.254: v3.8,66.51 4.44,65.88 v4.44,48.73 | v27.3,48.73 27.3,55.08 28.57,56.35 28.57,57.62 IC5.6
  Bottom 0.254: v3.8,66.51 7.62,66.51 OUT5-6.6 | v4.44,48.73 11.43,48.73 12.7,50 13.97,50 15.24,48.73 v27.3,48.73
N$91  (via drill 0.61)
  Top 0.254: v36.19,63.97 36.19,60.16 IC5.9 | v27.3,83.66 v27.3,63.97 | v12.06,83.02 12.06,68.41 11.43,67.78 8.25,67.78 8.25,68.41 OUT5-6.8
  Bottom 0.254: v27.3,63.97 v36.19,63.97 | v27.3,83.66 12.7,83.66 v12.06,83.02
N$92  (via drill 0.61)
  Top 0.254: v36.19,83.66 36.19,80.48 IC6.12 | v29.84,87.47 v29.84,83.66 | v7.62,87.47 7.62,81.11 6.98,80.48 6.98,70.95 7.62,70.32 10.79,70.32 10.79,70.95 OUT5-6.9
  Bottom 0.254: v29.84,83.66 v36.19,83.66 | v29.84,87.47 29.2,88.1 8.25,88.1 v7.62,87.47
N$93
  Bottom 0.254: IC6.15 29.2,78.58 31.11,76.67 33.65,76.67 37.46,72.86 37.46,69.69 30.47,69.69 29.84,70.32 29.84,75.4 12.7,75.4 11.43,74.13 OUT5-6.11
N$95
  Bottom 0.254: IC6.16 25.39,78.58 23.49,76.67 11.43,76.67 OUT5-6.13
N$96
  Bottom 0.254: IC6.19 17.77,78.58 16.5,77.3 13.33,77.3 11.43,79.21 OUT5-6.15
N$97
  Bottom 0.254: IC6.2 17.77,70.95 16.5,69.69 12.06,69.69 11.43,70.32 10.16,70.32 8.89,71.59 OUT5-6.10
N$98
  Top 0.254: IC6.5 26.03,72.86 24.76,74.13 24.76,80.48 20.95,84.29 9.52,84.29 9.52,76.03 8.25,74.77 OUT5-6.12
N$99
  Bottom 0.254: IC6.6 27.93,72.22 26.66,73.5 14.6,73.5 13.97,72.86 7.62,72.86 6.98,73.5 6.98,76.67 7.62,76.67 OUT5-6.14
N$100
  Bottom 0.254: IC6.9 35.55,72.22 31.74,76.03 12.06,76.03 11.43,75.4 10.16,75.4 9.52,76.03 9.52,78.58 8.25,78.58 OUT5-6.16
N$101  (via drill 0.61)
  Top 0.254: v81.91,60.16 82.55,59.52 v82.55,50 | v116.2,50 116.2,55.71 117.47,56.98 117.47,60.8 IN5-6.2
  Bottom 0.254: v81.91,60.16 87.62,60.16 88.26,60.8 93.97,60.8 94.61,60.16 IC15.3 | v82.55,50 103.5,50 104.77,48.73 105.41,48.73 106.04,49.37 108.58,49.37 109.21,50 v116.2,50
N$102
  Bottom 0.254: IC15.4 97.78,59.52 101.59,63.34 117.47,63.34 IN5-6.4
N$103  (via drill 0.61)
  Top 0.254: v116.2,56.98 115.56,57.62 115.56,65.24 116.83,66.51 IN5-6.6
  Bottom 0.254: v116.2,56.98 115.56,56.35 106.04,56.35 104.77,57.62 IC15.7
N$104  (via drill 0.61)
  Top 0.254: v108.58,68.41 108.58,61.43 107.94,60.8 107.94,59.52 IC15.8
  Bottom 0.254: v108.58,68.41 109.21,69.05 116.83,69.05 IN5-6.8
N$105  (via drill 0.61)
  Top 0.254: v114.3,86.19 113.66,86.83 113.66,87.47 113.02,87.47 111.75,86.19 111.75,83.66 107.94,79.84 IC16.13 | v121.28,84.92 121.28,72.22 120.64,71.59 IN5-6.9
  Bottom 0.254: v114.3,86.19 116.2,86.19 117.47,84.92 v121.28,84.92
N$106  (via drill 0.61)
  Top 0.254: v104.77,84.92 104.77,80.48 IC16.14 | v115.56,84.92 v115.56,75.4
  Bottom 0.254: v104.77,84.92 v115.56,84.92 | v115.56,75.4 118.1,75.4 118.74,74.77 120.01,74.77 IN5-6.11
N$107  (via drill 0.61)
  Top 0.254: v97.15,84.92 97.15,80.48 IC16.17 | v113.02,86.19 113.66,85.56 113.66,83.66 114.93,82.39 114.93,76.03 114.3,75.4 114.3,74.77 115.56,73.5 115.56,72.22 116.2,71.59 v116.2,67.78
  Bottom 0.254: v97.15,84.92 103.5,84.92 104.77,86.19 v113.02,86.19 | v116.2,67.78 120.64,67.78 123.82,70.95 123.82,76.03 123.19,76.67 120.64,76.67 IN5-6.13
N$108
  Bottom 0.254: IC16.18 95.24,79.84 96.52,81.11 117.47,81.11 119.38,79.21 IN5-6.15
N$109
  Bottom 0.254: IC15.13 107.94,65.88 109.21,64.61 116.2,64.61 116.83,65.24 120.64,65.24 121.28,64.61 121.28,62.06 120.01,62.06 IN5-6.1
N$110  (via drill 0.61)
  Top 0.254: v104.77,62.06 104.77,65.24 IC15.14
  Bottom 0.254: v104.77,62.06 116.2,62.06 116.83,62.7 118.1,62.7 118.74,63.34 120.01,63.34 IN5-6.3
N$111  (via drill 0.61)
  Top 0.254: v88.26,64.61 88.26,73.5 v88.89,74.13 | v122.55,72.86 v122.55,66.51
  Bottom 0.254: v88.26,64.61 95.24,64.61 95.88,65.24 97.15,65.24 IC15.17 | v88.89,74.13 89.53,74.13 90.16,74.77 111.75,74.77 113.66,72.86 v122.55,72.86 | v122.55,66.51 120.64,66.51 IN5-6.5
N$112
  Top 0.254: IC15.18 94.61,67.78 95.88,69.05 95.88,85.56 98.42,88.1 118.74,88.1 118.74,70.95 120.01,69.69 IN5-6.7
N$113
  Bottom 0.254: IC8.19 55.88,79.84 54.61,81.11 51.43,81.11 49.53,79.21 OUT7-8.15
N$114
  Bottom 0.254: IC8.16 63.5,78.58 62.23,77.3 48.89,77.3 OUT7-8.13
N$115
  Bottom 0.254: IC8.15 66.67,77.94 64.13,75.4 50.8,75.4 49.53,74.13 OUT7-8.11
N$116  (via drill 0.61)
  Top 0.254: v74.29,83.66 74.29,80.48 IC8.12 | v50.16,83.02 50.16,72.22 49.53,71.59 OUT7-8.9
  Bottom 0.254: v74.29,83.66 73.02,83.66 72.38,83.02 64.77,83.02 64.13,82.39 50.8,82.39 v50.16,83.02
N$117
  Bottom 0.254: IC8.2 55.88,70.95 54.61,69.69 50.16,69.69 49.53,70.32 48.26,70.32 46.98,71.59 OUT7-8.10
N$118  (via drill 0.61)
  Top 0.254: v64.13,76.67 64.13,72.86 IC8.5
  Bottom 0.254: v64.13,76.67 57.78,76.67 57.15,76.03 50.16,76.03 49.53,75.4 47.62,75.4 46.98,74.77 46.35,74.77 OUT7-8.12
N$119
  Top 0.254: IC8.6 66.67,72.86 65.4,74.13 65.4,80.48 61.59,84.29 47.62,84.29 47.62,78.58 46.35,77.3 OUT7-8.14
N$120
  Bottom 0.254: IC8.9 73.66,72.22 72.38,73.5 52.7,73.5 52.07,72.86 45.72,72.86 45.08,73.5 45.08,79.21 45.72,79.21 OUT7-8.16
N$121  (via drill 0.61)
  Top 0.254: v73.02,34.76 73.02,44.92 72.38,45.55 72.38,56.98 73.66,58.25 IC7.9 | v43.18,34.76 43.18,39.84 43.81,40.48 43.81,60.8 41.91,62.7 v41.91,69.69
  Bottom 0.254: v43.18,34.76 v73.02,34.76 | v41.91,69.69 41.91,69.05 45.72,69.05 OUT7-8.8
N$122  (via drill 0.61)
  Top 0.254: v47.62,39.84 47.62,48.09 50.16,50.63 50.16,55.71 49.53,56.35 49.53,58.89 47.62,60.8 47.62,62.06 46.98,62.7 45.72,62.7 45.08,63.34 45.08,65.88 45.72,66.51 OUT7-8.6 | v65.4,39.84 65.4,54.45 66.67,55.71 66.67,57.62 IC7.6
  Bottom 0.254: v47.62,39.84 47.62,39.2 60.96,39.2 61.59,39.84 v65.4,39.84
N$123
  Top 0.254: IC7.5 64.13,60.16 65.4,61.43 65.4,67.78 62.86,70.32 62.86,80.48 62.23,81.11 52.7,81.11 52.7,71.59 51.43,70.32 47.62,70.32 47.62,65.88 46.35,64.61 OUT7-8.4
OSEL
  Bottom 0.254: IC10.18 64.77,44.28 67.94,47.46 77.46,47.46 78.1,48.09 78.1,50.63 76.83,50.63 JP1.3
OUT00
  Bottom 0.254: IC1.11 38.1,16.34 34.92,19.52 34.92,26.5 36.83,26.5 37.46,27.14 37.46,30.31 46.98,30.31 48.26,29.04 IC10.1
OUT01
  Bottom 0.254: IC2.11 39.37,27.77 40.64,26.5 49.53,26.5 50.8,27.77 IC10.2
OUT02
  Bottom 0.254: IC3.11 39.37,41.11 59.69,41.11 60.32,40.48 64.77,40.48 65.4,41.11 67.94,41.11 74.29,34.76 74.29,30.31 60.96,30.31 60.32,29.68 60.32,26.5 55.88,26.5 54.61,27.77 IC10.3
OUT03  (via drill 0.61)
  Top 0.254: v50.16,30.95 50.8,31.58 50.8,41.74 50.16,42.38 v50.16,46.82 | v40.64,46.82 38.73,48.73 38.73,52.54 IC4.11
  Bottom 0.254: v50.16,30.95 55.24,30.95 56.51,29.68 IC10.4 | v50.16,46.82 v40.64,46.82
OUT04  (via drill 0.61)
  Top 0.254: v52.7,32.22 52.07,32.85 52.07,41.74 52.7,42.38 v52.7,45.55 | v41.27,45.55 41.91,46.19 41.91,53.17 41.27,53.81 v41.27,62.06
  Bottom 0.254: v52.7,32.22 53.34,31.58 55.88,31.58 57.78,29.68 59.05,29.68 IC10.5 | v52.7,45.55 v41.27,45.55 | v41.27,62.06 38.73,64.61 38.73,65.24 IC5.11
OUT05
  Top 0.254: IC10.6 61.59,27.14 60.32,25.87 60.32,19.52 50.16,9.36 50.16,6.82 49.53,6.18 44.45,6.18 44.45,82.39 43.18,83.66 38.73,83.66 38.73,80.48 IC6.11
OUT06
  Top 0.254: IC10.7 64.77,27.77 67.94,24.6 67.94,6.82 70.48,4.28 75.56,4.28 75.56,63.97 76.83,65.24 IC7.11
OUT07  (via drill 0.61)
  Top 0.254: v67.94,45.55 67.94,29.68 67.3,29.04 IC10.8 | v80,47.46 79.37,48.09 79.37,78.58 v80,79.21
  Bottom 0.254: v67.94,45.55 67.94,46.19 77.46,46.19 78.1,45.55 v80,47.46 | v80,79.21 77.46,79.21 IC8.11
PIA-A0  (via drill 0.61)
  Top 0.254: 93.34,19.52 92.7,20.15 IC12.2 | 93.34,19.52 93.34,12.54 92.07,11.27 92.07,9.36 IC11.2 | 93.34,32.22 92.7,32.85 IC13.2 | 93.34,32.22 93.34,19.52 | 93.34,44.92 92.7,45.55 IC14.2 | 93.34,44.92 93.34,32.22 | 93.34,57.62 92.7,58.25 IC15.2 | 93.34,57.62 93.34,44.92 | 93.34,57.62 93.34,70.32 92.7,70.95 IC16.2 | IC8.3 59.05,70.32 59.05,69.05 57.78,67.78 57.78,60.16 58.41,59.52 IC7.3 58.41,58.25 57.78,57.62 v57.78,52.54 | IC1.3 20.95,9.36 20.95,11.27 22.22,12.54 22.22,16.98 21.58,17.61 21.58,20.15 IC2.3 21.58,21.42 21.58,22.7 22.22,23.33 22.22,29.68 21.58,30.31 21.58,32.85 IC3.3 21.58,34.12 21.58,35.39 22.22,36.03 22.22,42.38 21.58,43.02 21.58,45.55 IC4.3 21.58,46.82 21.58,48.09 22.22,48.73 v22.22,51.27 22.22,55.08 21.58,55.71 21.58,58.25 IC5.3 21.58,59.52 21.58,60.8 22.22,61.43 22.22,67.78 21.58,68.41 21.58,70.95 IC6.3
  Bottom 0.254: v22.22,51.27 45.72,51.27 CORE-IO.1 46.35,51.91 46.98,51.91 47.62,52.54 v57.78,52.54 | IC16.2 92.07,70.32 91.44,69.69 68.57,69.69 67.94,70.32 67.3,69.69 59.69,69.69 59.05,70.32 IC8.3
PIA-A1  (via drill 0.61)
  Top 0.254: IC11.5 99.69,9.36 99.69,11.27 100.96,12.54 100.96,16.98 100.32,17.61 100.32,20.15 IC12.5 100.32,21.42 100.32,22.7 100.96,23.33 100.96,29.68 100.32,30.31 100.32,32.85 IC13.5 100.32,34.12 100.32,35.39 100.96,36.03 100.96,42.38 100.32,43.02 100.32,45.55 IC14.5 100.32,46.82 100.32,48.09 100.96,48.73 v100.96,51.91 100.96,55.08 100.32,55.71 100.32,58.25 IC15.5 100.32,59.52 100.32,60.8 100.96,61.43 100.96,67.78 100.32,68.41 100.32,70.95 IC16.5 | IC8.4 61.59,70.32 61.59,69.05 62.86,67.78 62.86,60.16 62.23,59.52 IC7.4 61.59,57.62 61.59,56.35 v62.86,55.08 | v46.35,59.52 46.35,54.45 CORE-IO.2 | 24.76,19.52 24.12,20.15 IC2.4 | 24.76,19.52 24.76,12.54 23.49,11.27 23.49,9.36 IC1.4 | 24.76,32.22 24.12,32.85 IC3.4 | 24.76,19.52 24.76,32.22 | 24.76,44.92 24.12,45.55 IC4.4 | 24.76,32.22 24.76,44.92 | 24.76,57.62 24.12,58.25 IC5.4 | 24.76,44.92 24.76,57.62 | 24.76,57.62 24.76,70.32 24.12,70.95 IC6.4 | v42.54,44.28 v42.54,53.81
  Bottom 0.254: v46.35,59.52 50.8,59.52 51.43,60.16 52.7,60.16 53.34,60.8 60.96,60.8 61.59,60.16 IC7.4 | v42.54,53.81 45.72,53.81 CORE-IO.2 | v42.54,44.28 24.12,44.28 23.49,44.92 IC4.4 | v100.96,51.91 100.32,51.27 83.81,51.27 79.37,55.71 63.5,55.71 v62.86,55.08
PIA-A2
  Top 0.254: IC1.7 31.11,9.36 32.38,10.63 32.38,17.61 31.11,18.88 31.11,19.52 IC2.7 31.11,22.06 32.38,23.33 32.38,30.31 31.74,30.95 31.74,32.85 IC3.7 31.11,34.76 32.38,36.03 32.38,43.02 31.11,44.28 31.11,44.92 IC4.7 31.11,47.46 32.38,48.73 32.38,55.08 31.74,55.71 31.74,56.98 31.11,57.62 IC5.7 31.11,60.16 32.38,61.43 32.38,68.41 31.11,69.69 31.11,70.32 IC6.7 31.11,72.86 32.38,74.13 32.38,86.19 33.65,87.47 67.94,87.47 67.94,69.05 | 67.94,69.05 67.94,61.43 69.21,60.16 IC7.7 | 67.94,69.05 69.21,70.32 IC8.7 | 103.5,18.25 103.5,14.44 102.23,13.17 102.23,9.36 IC11.6 | 103.5,18.25 102.23,19.52 IC12.6 | 103.5,30.95 102.23,32.22 IC13.6 | 103.5,30.95 103.5,18.25 | 103.5,43.65 102.23,44.92 IC14.6 | 103.5,43.65 103.5,30.95 | 103.5,56.35 102.23,57.62 IC15.6 | 103.5,56.35 103.5,43.65 | 103.5,56.35 103.5,69.05 102.23,70.32 IC16.6
  Bottom 0.254: CORE-IO.3 48.26,51.27 46.98,50 35.55,50 34.92,50.63 34.29,50.63 31.11,47.46 IC4.7 | IC7.7 69.84,58.25 71.11,56.98 100.32,56.98 101.59,58.25 IC15.6
PIA-A3  (via drill 0.61)
  Top 0.254: IC16.9 109.85,70.32 109.85,69.69 110.48,69.05 110.48,68.41 111.12,67.78 111.12,65.24 110.48,64.61 110.48,59.52 IC15.9 110.48,58.25 110.48,55.71 111.12,55.08 111.12,52.54 110.48,51.91 110.48,46.82 IC14.9 109.85,44.92 109.85,44.28 110.48,43.65 110.48,43.02 111.12,42.38 111.12,39.84 110.48,39.2 110.48,34.12 IC13.9 109.85,32.22 109.85,31.58 110.48,30.95 110.48,30.31 111.12,29.68 111.12,27.14 110.48,26.5 110.48,21.42 IC12.9 109.85,19.52 109.85,18.88 110.48,18.25 110.48,17.61 111.12,16.98 111.12,9.36 110.48,8.73 IC11.9 109.21,7.46 106.67,4.92 v104.77,4.92 | IC8.8 72.38,70.95 72.38,68.41 73.02,67.78 73.02,60.16 72.38,59.52 IC7.8 71.75,57.62 71.75,46.19 70.48,44.92 v70.48,37.3 v70.48,5.55 | IC6.8 33.65,70.32 33.65,69.69 34.29,69.05 34.29,68.41 34.92,67.78 34.92,65.24 34.29,64.61 34.29,59.52 IC5.8 34.29,58.25 34.29,55.71 34.92,55.08 v34.92,49.37 34.92,48.73 34.29,48.09 34.29,46.82 IC4.8 33.65,44.92 33.65,44.28 34.29,43.65 34.29,43.02 34.92,42.38 34.92,39.84 34.29,39.2 34.29,37.3 | IC1.8 34.29,8.73 34.29,10.63 34.92,11.27 34.92,16.98 34.29,17.61 34.29,18.25 33.65,18.88 33.65,19.52 IC2.8 34.29,21.42 34.29,26.5 34.92,27.14 34.92,29.68 34.29,30.31 34.29,30.95 33.65,31.58 33.65,32.22 IC3.8 34.29,34.12 34.29,37.3 | v47.62,49.37 47.62,53.17 48.26,53.81 CORE-IO.4 | 34.29,37.3 v34.92,37.3
  Bottom 0.254: v34.92,49.37 v47.62,49.37 | v70.48,37.3 61.59,37.3 60.96,37.94 47.62,37.94 46.35,36.66 35.55,36.66 v34.92,37.3 | v104.77,4.92 104.13,5.55 101.59,5.55 100.96,4.92 100.32,5.55 v70.48,5.55
PIA-A4  (via drill 0.61)
  Top 0.254: IC11.12 109.85,16.98 109.85,17.61 108.58,18.88 108.58,22.06 109.85,23.33 109.85,27.14 IC12.12 109.85,29.68 109.85,30.31 108.58,31.58 108.58,34.76 109.85,36.03 109.85,39.84 IC13.12 109.85,42.38 109.85,43.02 108.58,44.28 108.58,47.46 109.85,48.73 109.85,52.54 IC14.12 109.85,55.08 109.85,55.71 108.58,56.98 108.58,60.16 109.85,61.43 109.85,65.24 IC15.12 109.85,67.78 109.85,68.41 108.58,69.69 | 108.58,69.69 108.58,72.86 109.85,74.13 109.85,77.94 IC16.12 | IC7.13 71.11,67.14 70.48,67.78 70.48,74.13 71.75,75.4 71.75,77.94 IC8.13 71.75,80.48 v71.75,85.56 | IC1.13 33.65,16.98 33.65,17.61 32.38,18.88 32.38,22.06 33.65,23.33 33.65,27.14 IC2.13 33.65,29.68 33.65,30.31 32.38,31.58 32.38,34.76 33.65,36.03 33.65,39.84 IC3.13 33.65,42.38 33.65,43.02 32.38,44.28 32.38,47.46 v33.65,48.73 33.65,52.54 IC4.13 33.65,55.08 33.65,55.71 32.38,56.98 32.38,60.16 33.65,61.43 33.65,65.24 IC5.13 33.65,67.78 33.65,68.41 32.38,69.69 32.38,72.86 33.65,74.13 33.65,77.94 IC6.13 33.65,80.48 v33.65,86.19 | 108.58,69.69 107.31,68.41 106.04,68.41 v106.04,64.61
  Bottom 0.254: v33.65,48.73 34.29,48.09 34.92,48.09 35.55,48.73 46.35,48.73 46.98,48.09 47.62,48.09 48.89,49.37 50.16,49.37 51.43,50.63 CORE-IO.5 | v71.75,85.56 68.57,85.56 67.3,86.83 34.29,86.83 v33.65,86.19 | v106.04,64.61 101.59,64.61 100.96,65.24 100.96,67.78 100.32,68.41 72.38,68.41 71.75,67.78 IC7.13
PIA-A5
  Top 0.254: IC1.14 31.11,16.98 29.84,18.25 29.84,23.33 31.11,24.6 31.11,27.14 IC2.14 31.11,29.68 31.11,30.95 29.84,32.22 29.84,43.65 | 29.84,43.65 31.11,42.38 IC3.14 | 29.84,43.65 29.84,51.27 | 29.84,51.27 31.11,52.54 IC4.14 | 29.84,63.97 31.11,65.24 IC5.14 | 29.84,51.27 29.84,63.97 | 29.84,63.97 29.84,76.67 31.11,77.94 IC6.14 31.11,80.48 31.74,81.11 31.74,86.83 33.02,88.1 69.21,88.1 69.21,80.48 IC8.14 | IC11.15 102.23,16.98 100.96,18.25 100.96,22.06 102.23,23.33 102.23,27.14 IC12.15 102.23,29.68 100.96,30.95 100.96,34.76 102.23,36.03 102.23,39.84 IC13.15 102.23,42.38 100.96,43.65 100.96,47.46 102.23,48.73 102.23,52.54 IC14.15 102.23,55.08 100.96,56.35 100.96,60.16 102.23,61.43 102.23,65.24 IC15.15 102.23,67.78 100.96,69.05 100.96,76.67 102.23,77.94 IC16.15
  Bottom 0.254: CORE-IO.6 50.8,53.81 49.53,55.08 42.54,55.08 39.37,51.91 33.02,51.91 31.74,53.17 IC4.14 | IC8.14 69.84,79.84 71.11,81.11 92.7,81.11 93.34,80.48 93.34,77.94 93.97,77.3 100.32,77.3 101.59,78.58 IC16.15 | IC7.14 69.84,67.14 71.75,69.05 100.96,69.05 102.23,67.78 IC15.15
PIA-A6  (via drill 0.61)
  Top 0.254: IC1.17 23.49,16.98 23.49,17.61 22.22,18.88 22.22,22.06 23.49,23.33 23.49,27.14 IC2.17 23.49,29.68 23.49,30.31 22.22,31.58 22.22,34.76 23.49,36.03 23.49,39.84 IC3.17 23.49,42.38 23.49,43.02 22.22,44.28 22.22,47.46 23.49,48.73 23.49,52.54 IC4.17 23.49,55.08 23.49,55.71 22.22,56.98 22.22,60.16 23.49,61.43 23.49,65.24 IC5.17 23.49,67.78 23.49,68.41 22.22,69.69 22.22,72.86 23.49,74.13 23.49,77.94 IC6.17 | IC8.17 61.59,77.94 61.59,75.4 60.32,74.13 60.32,67.78 60.96,67.14 IC7.17 61.59,65.24 v61.59,62.7 | CORE-IO.7 53.34,51.27 52.7,51.91 52.7,54.45 50.16,56.98 v50.16,62.7 v50.16,67.78 | IC11.16 99.69,16.98 99.69,17.61 98.42,18.88 98.42,22.06 99.69,23.33 99.69,27.14 IC12.16 99.69,29.68 99.69,30.31 98.42,31.58 98.42,34.76 99.69,36.03 99.69,39.84 IC13.16 99.69,42.38 99.69,43.02 98.42,44.28 98.42,47.46 99.69,48.73 99.69,52.54 IC14.16 99.69,55.08 99.69,55.71 98.42,56.98 98.42,60.16 99.69,61.43 99.69,65.24 IC15.16 99.69,67.78 99.69,68.41 98.42,69.69 98.42,72.86 99.69,74.13 99.69,77.94 IC16.16
  Bottom 0.254: v50.16,62.7 v61.59,62.7 62.86,61.43 76.83,61.43 77.46,62.06 85.72,62.06 86.99,63.34 88.26,63.34 88.89,63.97 95.88,63.97 96.52,64.61 99.05,64.61 99.69,65.24 IC15.16 | v50.16,67.78 45.72,67.78 45.08,68.41 24.12,68.41 23.49,67.78 IC5.17
PIA-A7  (via drill 0.61)
  Top 0.254: IC11.19 92.07,16.98 92.07,17.61 90.8,18.88 90.8,22.06 92.07,23.33 92.07,27.14 IC12.19 92.07,29.68 92.07,30.31 90.8,31.58 90.8,34.76 92.07,36.03 92.07,39.84 IC13.19 92.07,42.38 92.07,43.02 90.8,44.28 90.8,47.46 92.07,48.73 92.07,52.54 IC14.19 92.07,55.08 92.07,55.71 90.8,56.98 90.8,60.16 92.07,61.43 92.07,65.24 IC15.19 92.07,67.78 92.07,68.41 90.8,69.69 90.8,72.86 92.07,74.13 92.07,77.94 IC16.19 | v57.78,69.05 57.78,74.13 59.05,75.4 59.05,77.94 IC8.18 | IC1.18 20.95,16.98 20.95,17.61 19.68,18.88 19.68,22.06 20.95,23.33 20.95,27.14 IC2.18 20.95,29.68 20.95,30.31 19.68,31.58 19.68,34.76 20.95,36.03 20.95,39.84 IC3.18 20.95,42.38 20.95,43.02 19.68,44.28 19.68,47.46 20.95,48.73 20.95,52.54 IC4.18 20.95,55.08 20.95,55.71 19.68,56.98 19.68,60.16 20.95,61.43 20.95,65.24 IC5.18 20.95,67.78 20.95,68.41 19.68,69.69 19.68,72.86 20.95,74.13 20.95,77.94 IC6.18 | v60.32,55.08 v60.32,56.35 60.32,61.43 59.05,62.7 59.05,65.24 IC7.18
  Bottom 0.254: v57.78,69.05 59.05,67.78 IC7.18 | 53.97,54.45 52.7,54.45 51.43,55.71 21.58,55.71 20.95,55.08 IC4.18 | 53.97,54.45 CORE-IO.8 53.97,54.45 | v60.32,55.08 54.61,55.08 53.97,54.45 | v60.32,56.35 90.8,56.35 92.07,55.08 IC14.19
PIA-B0  (via drill 0.61)
  Top 0.254: IC10.23 51.43,42.38 51.43,30.95 50.16,29.68 50.16,27.14 51.43,25.87 51.43,24.6 IC9.23 | v60.32,41.74 60.32,46.82 60.96,47.46 60.96,51.27 CORE-IO.13
  Bottom 0.254: v60.32,41.74 52.07,41.74 51.43,42.38 IC10.23
PIA-B1  (via drill 0.61)
  Top 0.254: IC9.22 53.97,24.6 53.97,25.23 52.7,26.5 52.7,29.68 53.97,30.95 53.97,42.38 IC10.22 53.97,44.92 v53.97,49.37 | v62.86,49.37 62.86,51.91 62.23,52.54 62.23,53.81 CORE-IO.14
  Bottom 0.254: v53.97,49.37 v62.86,49.37
PIA-B2  (via drill 0.61)
  Top 0.254: IC10.21 56.51,42.38 56.51,30.95 55.24,29.68 55.24,26.5 56.51,25.23 56.51,24.6 IC9.21 | v64.13,46.19 64.13,50.63 CORE-IO.15
  Bottom 0.254: v64.13,46.19 63.5,45.55 57.15,45.55 56.51,44.92 IC10.21
PIA-B3  (via drill 0.61)
  Top 0.254: IC9.20 59.05,24.6 59.05,25.23 57.78,26.5 57.78,29.68 59.05,30.95 59.05,42.38 IC10.20 59.05,44.92 59.05,46.82 60.32,48.09 v60.32,52.54
  Bottom 0.254: v60.32,52.54 63.5,52.54 64.13,53.17 CORE-IO.16
PIA-B4
  Bottom 0.254: JP1.1 76.83,49.37 75.56,50.63 75.56,51.91 76.19,52.54 77.46,52.54 78.1,53.17 78.1,55.08 68.57,55.08 67.94,54.45 67.94,51.91 66.67,51.91 CORE-IO.17
PIA-B5  (via drill 0.61)
  Top 0.254: v67.94,48.73 67.94,51.91 67.3,52.54 67.3,53.81 CORE-IO.18
  Bottom 0.254: v67.94,48.73 73.66,48.73 JP1.2
PIA-B6
  Bottom 0.254: JP1.5 76.19,53.81 74.92,52.54 71.11,52.54 69.84,51.27 CORE-IO.19
PIA-B7
  Bottom 0.254: JP1.6 73.66,53.81 69.84,53.81 CORE-IO.20
VCC  (via drill 0.61)
  Top 0.508: v86.99,13.17 86.99,15.08 BYP11.1 86.99,16.34 86.99,18.25 88.26,19.52 88.26,23.33 89.53,24.6 89.53,27.14 IC12.20 | v84.45,28.41 v84.45,41.11 v84.45,53.81 | IC15.20 89.53,65.24 89.53,62.7 88.26,61.43 88.26,57.62 86.99,56.35 86.99,54.45 BYP14.1 | v89.53,75.4 89.53,77.94 IC16.20 | IC16.11 112.39,77.94 v112.39,75.4 114.93,72.86 v114.93,66.51 v114.93,53.81 v114.93,41.11 v114.93,28.41 v114.93,15.71 | BYP15.1 86.99,67.14 86.99,72.22 85.72,73.5 85.72,77.3 86.35,77.94 86.99,77.94 86.99,78.58 BYP16.1 | BYP1.1 13.33,16.34 13.33,18.88 14.6,20.15 14.6,22.7 15.87,23.96 15.87,27.14 IC2.20 | IC3.20 15.87,39.84 v15.87,37.3 15.87,36.66 14.6,35.39 14.6,30.95 13.33,29.68 13.33,29.04 BYP2.1 | BYP9.1 46.35,23.96 46.35,31.58 47.62,32.85 v47.62,36.03 47.62,37.94 48.89,39.2 48.89,42.38 IC10.24 48.89,44.92 v48.89,48.09 | IC8.20 53.97,77.94 53.97,74.77 55.24,73.5 55.24,67.78 54.61,67.14 IC7.20 53.97,65.24 53.97,62.06 52.7,60.8 v52.7,55.71 | v59.05,56.35 59.05,54.45 CORE-IO.12 59.05,53.17 59.05,51.91 CORE-IO.11 59.05,50.63 v59.05,48.09 | BYP4.1 13.33,54.45 13.33,55.08 14.6,56.35 14.6,60.8 15.87,62.06 15.87,65.24 IC5.20 15.87,67.78 15.87,68.41 17.14,69.69 17.14,72.86 15.87,74.13 15.87,77.94 IC6.20 | v48.89,10.63 48.89,22.06 IC9.24
  Bottom 0.508: BYP11.1 87.62,15.71 88.89,15.71 IC11.20 | v86.99,13.17 82.55,13.17 BYP17.1 81.27,13.17 76.83,13.17 74.29,10.63 v48.89,10.63 | BYP15.1 87.62,66.51 88.89,66.51 IC15.20 | IC14.20 88.89,53.81 87.62,53.81 BYP14.1 86.35,53.81 v84.45,53.81 | IC12.20 88.89,28.41 87.62,28.41 BYP12.1 86.35,28.41 v84.45,28.41 | IC13.20 88.89,41.11 87.62,41.11 BYP13.1 86.35,41.11 v84.45,41.11 | BYP16.1 87.62,79.21 88.89,79.21 IC16.20 | v89.53,75.4 v112.39,75.4 | v114.93,53.81 113.02,53.81 IC14.11 | v114.93,66.51 113.02,66.51 IC15.11 | v114.93,15.71 113.02,15.71 IC11.11 | v114.93,28.41 113.02,28.41 IC12.11 | v114.93,41.11 113.02,41.11 IC13.11 | BYP3.1 13.97,41.11 15.24,41.11 IC3.20 | BYP1.1 13.97,15.71 15.24,15.71 IC1.20 | BYP2.1 13.97,28.41 15.24,28.41 IC2.20 | BYP9.1 46.98,23.33 48.26,23.33 IC9.24 | IC10.24 48.26,43.65 46.98,43.65 BYP10.1 | BYP7.1 52.07,66.51 53.34,66.51 IC7.20 | BYP8.1 52.07,79.21 53.34,79.21 IC8.20 | BYP6.1 13.97,79.21 15.24,79.21 IC6.20 | BYP5.1 13.97,66.51 15.24,66.51 IC5.20 | BYP4.1 13.97,53.81 15.24,53.81 IC4.20 15.87,55.08 16.5,55.71 20.31,55.71 20.95,56.35 52.7,56.35 | v59.05,56.35 52.7,56.35 | 52.7,56.35 v52.7,55.71 | v48.89,48.09 v59.05,48.09 | v15.87,37.3 16.5,37.94 25.39,37.94 27.3,36.03 v47.62,36.03

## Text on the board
tPlace: I/O Board | +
